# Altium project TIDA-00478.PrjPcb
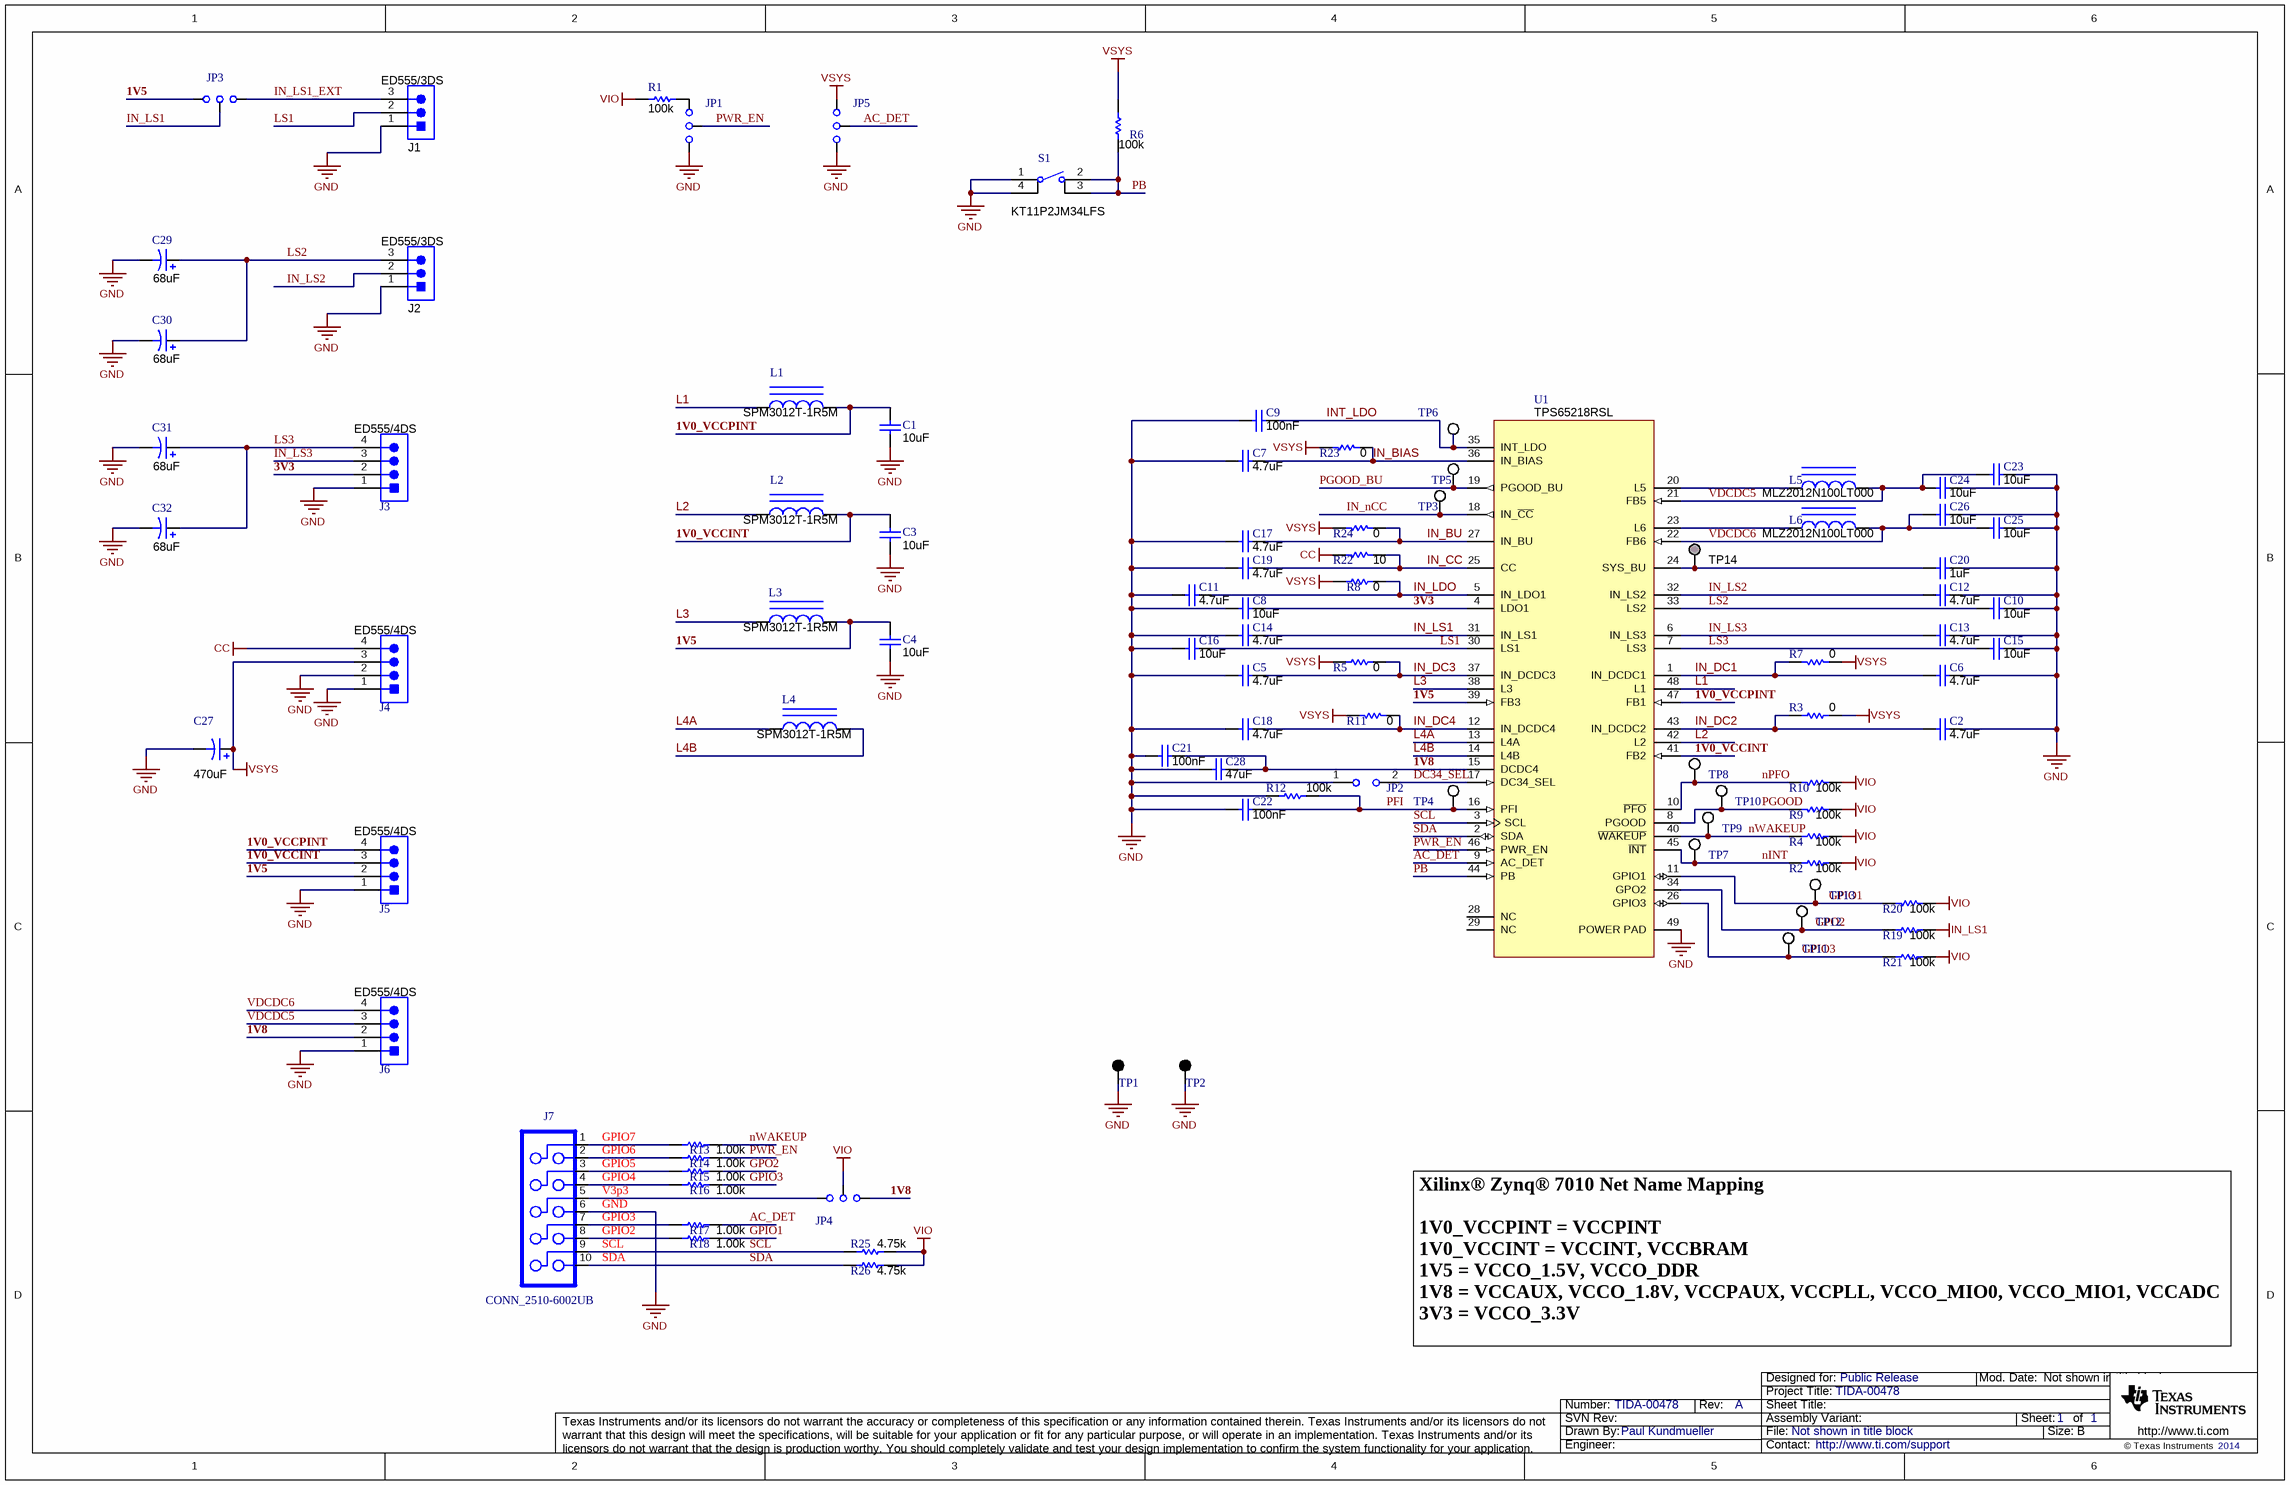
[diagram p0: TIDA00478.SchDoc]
CopyrightYear: 2014; PCB_Layout: Greg Watkins; PCB_Rev: A; PRJ_Customer: Public Release; PRJ_Number: TIDA-00478; PRJ_Title: TIDA-00478; SCH_Rev: A; TechSupport: http://www.ti.com/support
2 sheets, 111 parts. Net scope: global (net labels, ports and power ports of the same name join across sheets).
Board file: TIDA00478.PcbDoc
Sheets:
  TIDA00478.SchDoc
  TIDA00478_Hardware.SchDoc

## Sheet TIDA00478.SchDoc
size 431 x 279 mm; Date: Not shown in title block; ApprovedBy: Not shown in title block; CheckedBy: Not shown in title block; Author: Not shown in title block; CompanyName: Not shown in title block; DrawnBy: Paul Kundmueller; Organization: Not shown in title block; Address1: Not shown in title block; Address2: Not shown in title block; Address3: Not shown in title block; Address4: Not shown in title block; DocumentNumber: 1; Revision: Use project parameter SCH_Rev; SheetNumber: 1; SheetTotal: 1; PageSetup: Record=PageOptions|CenterHorizontal=True|CenterVertical=True|PrintScale=1.00|XCorrection=1.00|YCorrection=1.00|PrintKind=0|BorderSize=5000000|LeftOffset=0|BottomOffset=0|Orientation=2|PaperLength=1000|PaperWidth=1000|Scale=100|PaperSource=15|PrintQuality=600|MediaType=1|DitherType=10|PaperKind=Letter|PrintScaleMode=1

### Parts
C1  value 10uF  [0805]  (hidden comment: C2012X7R0J106K125AB)
C2  value 4.7uF  [0805]  (hidden comment: C2012X7R1A475K125AC)
C3  value 10uF  [0805]  (hidden comment: C2012X7R0J106K125AB)
C4  value 10uF  [0805]  (hidden comment: C2012X7R0J106K125AB)
C5  value 4.7uF  [0805]  (hidden comment: C2012X7R1A475K125AC)
C6  value 4.7uF  [0805]  (hidden comment: C2012X7R1A475K125AC)
C7  value 4.7uF  [0805]  (hidden comment: C2012X7R1A475K125AC)
C8  value 10uF  [0805]  (hidden comment: C2012X7R0J106K125AB)
C9  value 100nF  [0805]  (hidden comment: C0805C104K8RACTU)
C10  value 10uF  [0805]  (hidden comment: C2012X7R1A106K125AC)
C11  value 4.7uF  [0805]  (hidden comment: C2012X7R1A475K125AC)
C12  value 4.7uF  [0805]  (hidden comment: C2012X7R1A475K125AC)
C13  value 4.7uF  [0805]  (hidden comment: C2012X7R1C475K125AE)
C14  value 4.7uF  [0805]  (hidden comment: C2012X7R1A475K125AC)
C15  value 10uF  [0805]  (hidden comment: CL21B106KOQNNNE)
C16  value 10uF  [0805]  (hidden comment: C2012X7R1A106K125AC)
C17  value 4.7uF  [0805]  (hidden comment: C2012X7R1A475K125AC)
C18  value 4.7uF  [0805]  (hidden comment: C2012X7R1A475K125AC)
C19  value 4.7uF  [0805]  (hidden comment: C2012X7R1A475K125AC)
C20  value 1uF  [0805]  (hidden comment: CL21B105KPFNNNE)
C21  value 100nF  [0805]  (hidden comment: C0805C104K8RACTU)
C22  value 100nF  [0805]  (hidden comment: C0805C104K8RACTU)
C23  value 10uF  [0805]  (hidden comment: C2012X7R1A106K125AC)
C24  value 10uF  [0805]  (hidden comment: C2012X7R1A106K125AC)
C25  value 10uF  [0805]  (hidden comment: C2012X7R1A106K125AC)
C26  value 10uF  [0805]  (hidden comment: C2012X7R1A106K125AC)
C27  value 470uF  [SM_RADIAL_G]  (hidden comment: EEE-1EA471UAP)
C28  value 47uF  [0805]  (hidden comment: C2012X5R1A476M125AC)
C29  value 68uF  [6032-28]  (hidden comment: T495C686M016ZTE250)
C30  value 68uF  [6032-28]  (hidden comment: T495C686M016ZTE250)
C31  value 68uF  [6032-28]  (hidden comment: T495C686M016ZTE250)
C32  value 68uF  [6032-28]  (hidden comment: T495C686M016ZTE250)
J1  ED555/3DS  [TERM_BLK_ED555-3DS]
J2  ED555/3DS  [TERM_BLK_ED555-3DS]
J3  ED555/4DS  [TERM_BLK_ED555-4DS]
J4  ED555/4DS  [TERM_BLK_ED555-4DS]
J5  ED555/4DS  [TERM_BLK_ED555-4DS]
J6  ED555/4DS  [TERM_BLK_ED555-4DS]
J7  CONN_2510-6002UB  [CONN_2510-6002UB]
JP1  PWR_EN  [HDR100_1X3]  (value not drawn)
JP2  DC34_SEL  [HDR100_1X2]  (value not drawn)
JP3  IN_LS1  [HDR100_1X3]  (value not drawn)
JP4  VIO  [HDR100_1X3]  (value not drawn)
JP5  AC_DET  [HDR100_1X3]  (value not drawn)
L1  SPM3012T-1R5M  [SPM3012]
L2  SPM3012T-1R5M  [SPM3012]
L3  SPM3012T-1R5M  [SPM3012]
L4  SPM3012T-1R5M  [SPM3012]
L5  MLZ2012N100LT000  [0805_145]
L6  MLZ2012N100LT000  [0805_145]
R1  ValueDisplayed: 100k  [0603]  (hidden comment: CRCW0603100KFKEA)
R2  ValueDisplayed: 100k  [0603]  (hidden comment: CRCW0603100KFKEA)
R3  value 0  [0805_HV]  (hidden comment: CRCW08050000Z0EAHP)
R4  ValueDisplayed: 100k  [0603]  (hidden comment: CRCW0603100KFKEA)
R5  value 0  [0805_HV]  (hidden comment: CRCW08050000Z0EAHP)
R6  ValueDisplayed: 100k  [0603]  (hidden comment: CRCW0603100KFKEA)
R7  value 0  [0805_HV]  (hidden comment: CRCW08050000Z0EAHP)
R8  value 0  [0805_HV]  (hidden comment: CRCW08050000Z0EAHP)
R9  ValueDisplayed: 100k  [0603]  (hidden comment: CRCW0603100KFKEA)
R10  ValueDisplayed: 100k  [0603]  (hidden comment: CRCW0603100KFKEA)
R11  value 0  [0805_HV]  (hidden comment: CRCW08050000Z0EAHP)
R12  ValueDisplayed: 100k  [0603]  (hidden comment: CRCW0603100KFKEA)
R13  ValueDisplayed: 1.00k  [0603]  (hidden comment: CRCW06031K00FKEA)
R14  ValueDisplayed: 1.00k  [0603]  (hidden comment: CRCW06031K00FKEA)
R15  ValueDisplayed: 1.00k  [0603]  (hidden comment: CRCW06031K00FKEA)
R16  ValueDisplayed: 1.00k  [0603]  (hidden comment: CRCW06031K00FKEA)
R17  ValueDisplayed: 1.00k  [0603]  (hidden comment: CRCW06031K00FKEA)
R18  ValueDisplayed: 1.00k  [0603]  (hidden comment: CRCW06031K00FKEA)
R19  ValueDisplayed: 100k  [0603]  (hidden comment: CRCW0603100KFKEA)
R20  ValueDisplayed: 100k  [0603]  (hidden comment: CRCW0603100KFKEA)
R21  ValueDisplayed: 100k  [0603]  (hidden comment: CRCW0603100KFKEA)
R22  ValueDisplayed: 10  [0603]  (hidden comment: CRCW060310R0JNEAHP)
R23  value 0  [0805_HV]  (hidden comment: CRCW08050000Z0EAHP)
R24  value 0  [0805_HV]  (hidden comment: CRCW08050000Z0EAHP)
R25  ValueDisplayed: 4.75k  [0603]  (hidden comment: CRCW06034K75FKEA)
R26  ValueDisplayed: 4.75k  [0603]  (hidden comment: CRCW06034K75FKEA)
S1  KT11P2JM34LFS  [SW_KT11P2JM]
TP1  GND  [Keystone5001]  (value not drawn)
TP2  GND  [Keystone5001]  (value not drawn)
TP3  IN_nCC  [Keystone5002]  (value not drawn)
TP4  PFI  [Keystone5002]  (value not drawn)
TP5  PGOOD_BU  [Keystone5002]  (value not drawn)
TP6  INT_LDO  [Keystone5002]  (value not drawn)
TP7  nINT  [Keystone5002]  (value not drawn)
TP8  nPFO  [Keystone5002]  (value not drawn)
TP9  nWAKEUP  [Keystone5002]  (value not drawn)
TP10  PGOOD  [Keystone5002]  (value not drawn)
TP11  GPIO3  [Keystone5002]  (value not drawn)
TP12  GPO2  [Keystone5002]  (value not drawn)
TP13  GPIO1  [Keystone5002]  (value not drawn)
TP14  SYS_BU  [TESTPOINT]  (value not drawn)  (no BOM)
U1  TPS65218RSL  [RSL0048B_NV]

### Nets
CC: J4.4 R22.2
GND: C1.2 C2.2 C3.2 C4.2 C5.2 C6.1 C7.2 C8.1 C9.2 C10.2 C11.1 C12.2 C13.1 C14.2 C15.1 C16.2 C17.2 C18.1 C19.2 C20.1 C21.1 C22.1 C23.1 C24.1 C25.1 C26.1 C27.2(-) C28.1 C29.2(-) C30.2(-) C31.2(-) C32.2(-) J1.1 J2.1 J3.1 J4.1 J4.2 J5.1 J6.1 J7.6 JP1.1 JP2.1 JP5.1 R12.1 S1.1 S1.4 TP1.1 TP2.1 U1.49(POWER_PAD)
IN_LS1: C14.1 JP3.2 R19.2 U1.31(IN_LS1)
VIO: JP4.2 R1.2 R2.2 R4.2 R9.1 R10.1 R20.1 R21.2 R25.2 R26.2
VSYS: C27.1(+) J4.3 JP5.3 R3.2 R5.2 R6.2 R7.1 R8.1 R11.1 R23.2 R24.2
1V0_VCCINT: C3.1 J5.3 L2.2 U1.41(FB2)
1V0_VCCPINT: C1.1 J5.4 L1.2 U1.47(FB1)
1V5: C4.1 J5.2 JP3.3 L3.2 U1.39(FB3)
1V8: C21.2 C28.2 J6.2 JP4.3 U1.15(DCDC4)
3V3: C8.2 J3.2 U1.4(LDO1)
AC_DET: JP5.2 R17.2 U1.9(AC_DET)
DC34_SEL: JP2.2 U1.17(DC34_SEL)
GPIO1: R18.2 R20.2 TP13.1 U1.11(GPIO1)
GPIO3: R16.2 R21.1 TP11.1 U1.26(GPIO3)
GPO2: R15.2 R19.1 TP12.1 U1.34(GPO2)
IN_BIAS: C7.1 R23.1 U1.36(IN_BIAS)
IN_BU: C17.1 R24.1 U1.27(IN_BU)
IN_CC: C19.1 R22.1 U1.25(CC)
IN_DC1: C6.2 R7.2 U1.1(IN_DCDC1)
IN_DC2: C2.1 R3.1 U1.43(IN_DCDC2)
IN_DC3: C5.1 R5.1 U1.37(IN_DCDC3)
IN_DC4: C18.2 R11.2 U1.12(IN_DCDC4)
IN_LDO: C11.2 R8.2 U1.5(IN_LDO1)
IN_LS1_EXT: J1.3 JP3.1
IN_LS2: C12.1 J2.2 U1.32(IN_LS2)
IN_LS3: C13.2 J3.3 U1.6(IN_LS3)
IN_nCC: TP3.1 U1.18(IN_~{CC})
INT_LDO: C9.1 TP6.1 U1.35(INT_LDO)
L1: L1.1 U1.48(L1)
L2: L2.1 U1.42(L2)
L3: L3.1 U1.38(L3)
L4A: L4.2 U1.13(L4A)
L4B: L4.1 U1.14(L4B)
LS1: C16.1 J1.2 U1.30(LS1)
LS2: C10.1 C29.1(+) C30.1(+) J2.3 U1.33(LS2)
LS3: C15.2 C31.1(+) C32.1(+) J3.4 U1.7(LS3)
nINT: R2.1 TP7.1 U1.45(~{INT})
nPFO: R10.2 TP8.1 U1.10(~{PFO})
nWAKEUP: R4.1 R13.2 TP9.1 U1.40(~{WAKEUP})
PB: R6.1 S1.2 S1.3 U1.44(PB)
PFI: C22.2 R12.2 TP4.1 U1.16(PFI)
PGOOD: R9.2 TP10.1 U1.8(PGOOD)
PGOOD_BU: TP5.1 U1.19(PGOOD_BU)
PWR_EN: JP1.2 R14.2 U1.46(PWR_EN)
SCL: J7.9 R25.1 U1.3(SCL)
SDA: J7.10 R26.1 U1.2(SDA)
VDCDC5: C23.2 C24.2 J6.3 L5.1 U1.21(FB5)
VDCDC6: C25.2 C26.2 J6.4 L6.1 U1.22(FB6)
NetC20_2: C20.2 TP14.1 U1.24(SYS_BU)
NetJ7_1: J7.1 R13.1
NetJ7_2: J7.2 R14.1
NetJ7_3: J7.3 R15.1
NetJ7_4: J7.4 R16.1
NetJ7_5: J7.5 JP4.1
NetJ7_7: J7.7 R17.1
NetJ7_8: J7.8 R18.1
NetJP1_3: JP1.3 R1.1
NetL5_2: L5.2 U1.20(L5)
NetL6_2: L6.2 U1.23(L6)

Not connected (* = marked no-connect by the designer): U1 28(NC) 29(NC)

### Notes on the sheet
- (near J7) GPIO7
- (near J7) GPIO6
- (near J7) GPIO5
- (near J7) GPIO4
- (near J7) V3p3
- (near J7) GND
- (near J7) GPIO3
- (near J7) GPIO2
- (near J7) SCL
- (near J7) SDA
- Xilinx® Zynq® 7010 Net Name Mapping
  1V0_VCCPINT = VCCPINT
  1V0_VCCINT = VCCINT, VCCBRAM
  1V5 = VCCO_1.5V, VCCO_DDR
  1V8 = VCCAUX, VCCO_1.8V, VCCPAUX, VCCPLL, VCCO_MIO0, VCCO_MIO1, VCCADC
  3V3 = VCCO_3.3V

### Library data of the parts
C1 C3 C4 C8 = Capacitor: CAP, CERM, 10F, 6.3V, X7R, 10%, 0805; Manufacturer: TDK; Polarized: N; U/M: EA
C2 C5-C7 C11 C12 C14 C17-C19 = Capacitor: CAP, CERM, 4.7uF, 10V, X7R, 10%, 0805; Manufacturer: TDK; Polarized: N; U/M: EA
C9 C21 C22 = Capacitor: CAP, CERM, 100nF, 10V, X7R, 10%, 0805; Manufacturer: Kemet; Polarized: N; U/M: EA
C10 C16 C23-C26 = Capacitor: CAP, CERM, 10uF, 10V, X7R, 10%, 0805; Manufacturer: TDK; Polarized: N; U/M: EA
C13 = Capacitor: CAP, CERM, 4.7uF, 16V, X7R, 10%, 0805; Manufacturer: TDK; Polarized: N; U/M: EA
C15 = Capacitor: CAP, CERM, 10uF, 16V, X7R, 10%, 0805; Manufacturer: Samsung; Polarized: N; U/M: EA
C20 = Capacitor: CAP, CERM, 1uF, 10V, X7R, 10%, 0805; Manufacturer: Samsung; Polarized: N; U/M: EA
C27 = Capacitor_Polarized: CAP, ALUM, 470uF, 25V, +/-20%, SMD; Manufacturer: Panasonic; Polarized: Y; U/M: EA
C28 = Capacitor: CAP, CERM, 47uF, 10V, X5R, 20%, 0805; Manufacturer: TDK; Polarized: N; U/M: EA
C29-C32 = Capacitor_Polarized: CAP, TANT, 68uF, 16V, +/-20%, 250mOhm ESR, SMT; Manufacturer: Kemet; Polarized: Y; U/M: EA
J1 J2 = ED555/3DS: Terminal Block, 6A, 3.5mm Pitch, 3-Pos, TH; Manufacturer: On-Shore Technology; SymbolCreator: a0799628; CompType: Connector; U/M: EA
J3-J6 = ED555/4DS: Terminal Block, 6A, 3.5mm Pitch, 4-Pos, TH; Manufacturer: On-Shore Technology; SymbolCreator: a0412235; CompType: Connector; U/M: EA
J7 = CONN_2510-6002UB: Connector, Male Straight 2x5 pin, 100mil spacing, 4 Wall; Manufacturer: 3M; Value: N2510-6002RB; area: 301.024
JP1 JP3-JP5 = JUMPER_3X100MIL: Header, Male 3-pin, 100mil spacing,; Manufacturer: Sullins; Value: PEC03SAAN; Area: 30000
JP2 = JUMPER_2X100MIL: Header, Male 2-pin, 100mil spacing,; Manufacturer: Sullins; Value: PEC02SAAN; Area: 20000
L1-L4 = SPM3012T-1R5M: Inductor, Shielded, Ferrite, 1.5uH, 2.8A, 0.09 ohm, SMD; Manufacturer: TDK; Ind_H: 1.5E-6; ValueDisplayed: 1.5µH; Imax_A: 2.8; Irms: 2.6A @ 40C rise; Isat: 2.8A @ 30% inductance drop; DCR_ohm: 0.09
L5 L6 = MLZ2012N100LT000: Inductor, Multilayer, Ferrite, 10uH, 0.5A, 0.3 ohm, SMD; Manufacturer: TDK; Ind_H: 10.0E-6; ValueDisplayed: 10µH; Imax_A: 0.5; Irms: 0.5A @ 20C rise; Isat: 0.11A @ 50% inductance drop; DCR_ohm: 0.3; Value1: 0.3 ohm
R1 R2 R4 R6 R9 R10 R12 R19-R21 = CRCW0603100KFKEA: RES, 100 k, 1%, 0.1 W, 0603; Manufacturer: Vishay-Dale; Value: 100k; CompType: Resistor; Res_ohm: 100000; Tolerance_%: 1; Power_W: 0.1; Value2: 0.1W; VDC_V: 75; TempCo: 100 ppm/C; EIA_Code: E96; U/M: EA
R3 R5 R7 R8 R11 R23 R24 = CRCW08050000Z0EAHP: RES, 0 ohm, 5%, 0.333W, 0805; Manufacturer: Vishay-Dale; CompType: Resistor; Value_Code: 0000; Tolerance_%: 5; Power_W: 0.333; TempCo: 200 ppm/C; EIA_Code: E24; U/M: EA
R13-R18 = CRCW06031K00FKEA: RES, 1.00 k, 1%, 0.1 W, 0603; Manufacturer: Vishay-Dale; Value: 1.00k; CompType: Resistor; Res_ohm: 1000; Value_Code: 1k00; Tolerance_%: 1; Power_W: 0.1; Value2: 0.1W; VDC_V: 75; TempCo: 100 ppm/C; EIA_Code: E96; U/M: EA
R22 = CRCW060310R0JNEAHP: RES, 10, 5%, 0.25 W, 0603; Manufacturer: Vishay-Dale; Value: 10; CompType: Resistor; Value_Code: 10R0; Tolerance_%: 5; Power_W: 0.25; Value2: 0.25W; VDC_V: 75; TempCo: 200 ppm/C; EIA_Code: E24; U/M: EA
R25 R26 = CRCW06034K75FKEA: RES, 4.75 k, 1%, 0.1 W, 0603; Manufacturer: Vishay-Dale; Value: 4.75k; CompType: Resistor; Res_ohm: 4750; Value_Code: 4k75; Tolerance_%: 1; Power_W: 0.1; Value2: 0.1W; VDC_V: 75; TempCo: 100 ppm/C; EIA_Code: E96; U/M: EA
S1 = KT11P2JM34LFS: Switch, Tactile, SPST-NO, 1VA, 32V, SMT; Manufacturer: C&K Components; SymbolCreator: a0412235; VDC_V: 32; SwitchFunction: Off-Mom; PositionCount: 1; CurrentRating_mA: 1000
TP1 TP2 = 5001: Test Point, Miniature, Black, TH; Manufacturer: Keystone; CompType: Test Point Loop; U/M: EA
TP3-TP13 = 5002: Test Point, Miniature, White, TH; Manufacturer: Keystone; CompType: Test Point Loop; U/M: EA
TP14 = TESTPOINT: TEST POINT.  No entry in BOM.
U1 = TPS65218RSL: Power Management for AM335x / AM437x ARM® Cortex™-A8 / A9 SOCs, RSL0048B; Alternate Manufacturer: None; Manufacturer: Texas Instruments; SymbolCreator: Altium; CompType: IC; U/M: EA

## Sheet TIDA00478_Hardware.SchDoc
size 431 x 279 mm; Date: Not shown in title block; ApprovedBy: Not shown in title block; CheckedBy: Not shown in title block; Author: Not shown in title block; CompanyName: Not shown in title block; Engineer: Not shown in title block; Organization: Not shown in title block; Address1: Not shown in title block; Address2: Not shown in title block; Address3: Not shown in title block; Address4: Not shown in title block; DocumentNumber: 1; Revision: Use project parameter SCH_Rev; SheetNumber: 1; SheetTotal: 1; PageSetup: Record=PageOptions|CenterHorizontal=True|CenterVertical=True|PrintScale=1.00|XCorrection=1.00|YCorrection=1.00|PrintKind=0|BorderSize=5000000|LeftOffset=0|BottomOffset=0|Orientation=2|PaperLength=1000|PaperWidth=1000|Scale=100|PaperSource=15|PrintQuality=600|MediaType=1|DitherType=10|PaperKind=Letter|PrintScaleMode=1
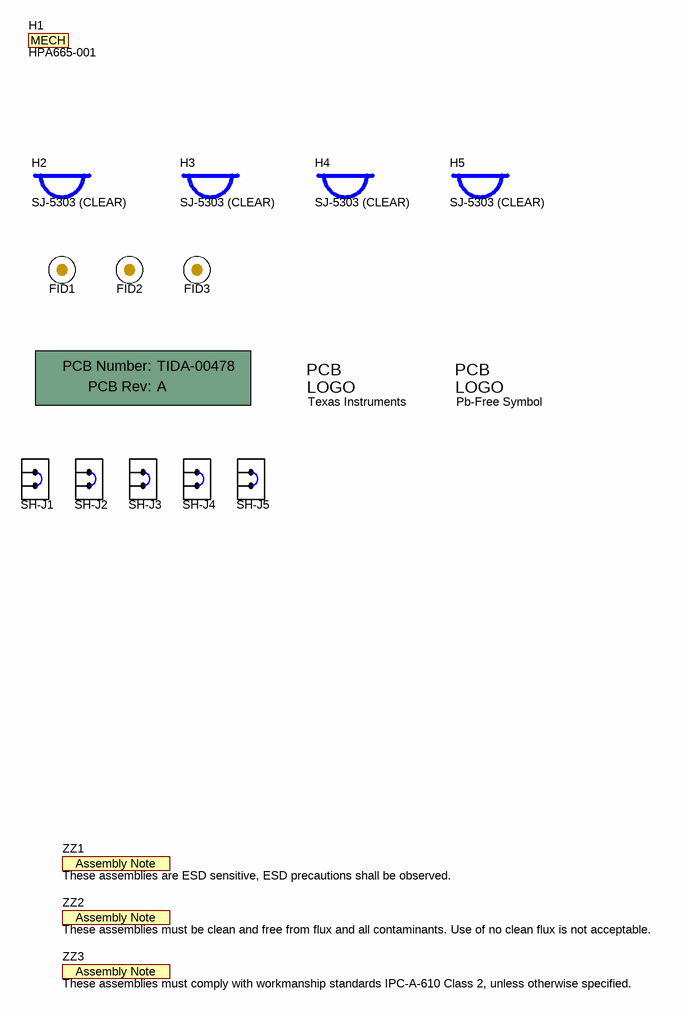
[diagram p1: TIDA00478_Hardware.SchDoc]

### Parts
!PCB  Printed Circuit Board  (value not drawn)  (mechanical)
FID1  Fiducial  [Fiducial10-20]  (value not drawn)
FID2  Fiducial  [Fiducial10-20]  (value not drawn)
FID3  Fiducial  [Fiducial10-20]  (value not drawn)
H1  HPA665-001  (mechanical)
H2  SJ-5303 (CLEAR)  [Bumpon_SJ5003Transparent]
H3  SJ-5303 (CLEAR)  [Bumpon_SJ5003Transparent]
H4  SJ-5303 (CLEAR)  [Bumpon_SJ5003Transparent]
H5  SJ-5303 (CLEAR)  [Bumpon_SJ5003Transparent]
Logo1  Texas Instruments  [TI_Stacked_Overlay_Small]  (no BOM)
Logo2  Pb-Free Symbol  [Pb-Free_Overlay_Small]  (no BOM)
SH-J1  SPC02SYAN  [SPC02SYAN]  (value not drawn)
SH-J2  SPC02SYAN  [SPC02SYAN]  (value not drawn)
SH-J3  SPC02SYAN  [SPC02SYAN]  (value not drawn)
SH-J4  SPC02SYAN  [SPC02SYAN]  (value not drawn)
SH-J5  SPC02SYAN  [SPC02SYAN]  (value not drawn)
ZZ1  These assemblies are ESD sensitive, ESD precautions shall be observed.  [AssemblyNote]  (no BOM)
ZZ2  These assemblies must be clean and free from flux and all contaminants. Use of no clean flux is not acceptable.  [AssemblyNote]  (no BOM)
ZZ3  These assemblies must comply with workmanship standards IPC-A-610 Class 2, unless otherwise specified.  [AssemblyNote]  (no BOM)

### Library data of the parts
!PCB = PCB: Manufacturer: Any; PartNumber: TIDA-00478; SymbolCreator: a0412235
FID1-FID3 = Fiducial: Fiducial mark.  There is nothing to buy or mount.; SymbolCreator: codlsc
H1 = MechPart: USB2ANY; Manufacturer: Texas Instruments; SymbolCreator: codlsc; CompType: Mechanical; U/M: EA
H2-H5 = SJ-5303 (CLEAR): Bumpon, Hemisphere, 0.44 X 0.20, Clear; Manufacturer: 3M; SymbolCreator: a0412235
Logo1 = TI_Logo: Texas Instrument Corporate Signature; SymbolCreator: a0412235
Logo2 = Pb-Free: SymbolCreator: a0412235
SH-J1-SH-J5 = SPC02SYAN: Shunt, 100mil, Flash Gold, Black; Manufacturer: Sullins Connector Solutions; Value: 1x2; Note: You can "mate" this to a header by matching the designator.  i.e. use SH-J3 for header J3
ZZ1-ZZ3 = AssemblyNote: SymbolCreator: codlsc

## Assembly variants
001: not fitted C27 C29 C30 C31 C32 FID1 FID2 FID3 R13 R14 R15 R16 R17 R18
